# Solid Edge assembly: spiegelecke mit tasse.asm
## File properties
Author: Dieter
Template: Normal.asm
Last saved by: Dieter
Revision: 3
Application: Solid Edge
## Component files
Spiegelecke.par
Tasse.par
